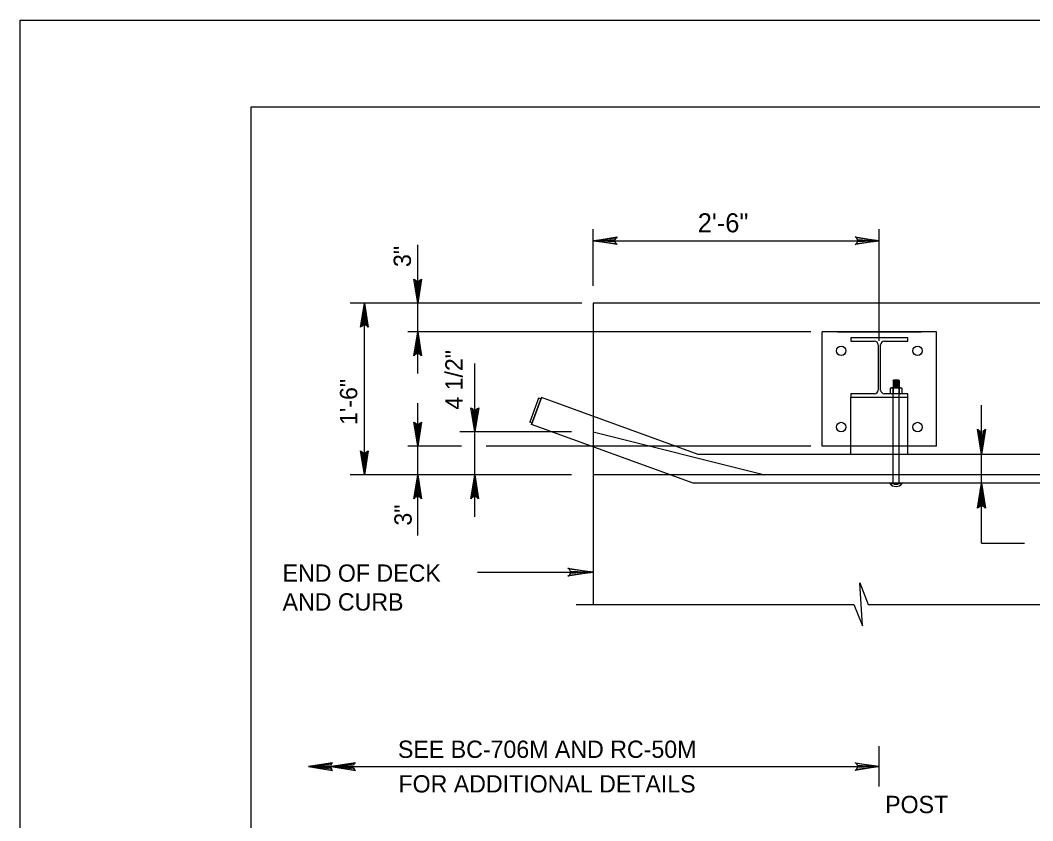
# Model space of a CAD drawing. Extents: x 641054 to 641910, y 298137 to 299325.
# Drawn here: x 641054.5 to 641229.9, y 299186.5 to 299325.4 of the extents above; entities that cross this region are included whole.
import ezdxf

# ---------------------------------------------------------------- set-up
doc = ezdxf.new("R2010")
doc.units = 0
for name, color, linetype in [('1', 7, 'Continuous'), ('2', 7, 'Continuous'), ('Default', 7, 'Continuous'), ('PLT-BNDY', 7, 'Continuous')]:
    doc.layers.add(name, color=color, linetype=linetype)

msp = doc.modelspace()

# ---------------------------------------------------------------- linework, layer by layer
at = {"layer": '1'}
for p, q in [((641205.74, 299262.92), (641205.83, 299263.01)), ((641205.74, 299262.92), (641205.74, 299261.63)), ((641205.74, 299262.92), (641206.77, 299262.92)), ((641205.74, 299262.66), (641206.77, 299262.66)), ((641205.74, 299262.4), (641206.77, 299262.4)), ((641205.82, 299262.79), (641206.69, 299262.79)), ((641205.82, 299262.53), (641206.69, 299262.53)), ((641205.82, 299262.27), (641206.69, 299262.27)), ((641205.83, 299263.01), (641206.69, 299263.01)), ((641206.77, 299262.92), (641206.69, 299263.01)), ((641206.77, 299262.92), (641206.77, 299261.63)), ((641205.4, 299261.63), (641205.26, 299261.55)), ((641205.26, 299261.55), (641205.26, 299260.69)), ((641205.4, 299260.61), (641205.26, 299260.69)), ((641205.4, 299261.63), (641207.12, 299261.63)), ((641207.12, 299260.61), (641205.4, 299260.61)), ((641205.74, 299262.14), (641206.77, 299262.14)), ((641205.74, 299261.89), (641206.77, 299261.89)), ((641205.74, 299261.55), (641205.74, 299260.69)), ((641205.82, 299262.02), (641206.69, 299262.02)), ((641205.82, 299261.76), (641206.69, 299261.76)), ((641206.77, 299261.55), (641206.77, 299260.69)), ((641207.12, 299261.63), (641207.25, 299261.55)), ((641207.12, 299260.61), (641207.25, 299260.69)), ((641207.25, 299261.55), (641207.25, 299260.69)), ((641206.82, 299245.06), (641205.69, 299245.06)), ((641104.45, 299195.95), (641203.36, 299195.95))]:
    msp.add_line(p, q, dxfattribs=at)
for centre, radius, start, end in [((641205.5, 299261.22), 0.409, 54.2974, 89.9999), ((641205.5, 299261.02), 0.409, 269.9985, 305.701), ((641206.26, 299259.85), 1.77, 73.0653, 106.9335), ((641206.26, 299262.39), 1.77, 253.0634, 286.9317), ((641207.01, 299261.22), 0.409, 89.9993, 125.7017), ((641207.01, 299261.02), 0.409, 234.2959, 269.9983)]:
    msp.add_arc(centre, radius, start, end, dxfattribs=at)
at = {"layer": '2'}
for p, q in [((641094.49, 298746.38), (641094.49, 299310.38)), ((641094.49, 299310.38), (641880.49, 299310.38)), ((641144.32, 299259.84), (641142.8, 299255.67)), ((641143.11, 299255.29), (641144.81, 299259.95)), ((641143.11, 299255.29), (641144.81, 299259.95)), ((641144.81, 299259.95), (641143.11, 299255.29)), ((641144.71, 299259.7), (641144.32, 299259.84)), ((641171.95, 299250.07), (641144.81, 299259.95)), ((641171.95, 299250.07), (641144.81, 299259.95)), ((641143.2, 299255.53), (641142.8, 299255.67)), ((641171.08, 299245.11), (641143.11, 299255.29)), ((641171.08, 299245.11), (641143.11, 299255.29)), ((641375.12, 299250.07), (641171.95, 299250.07)), ((641375.12, 299245.11), (641171.08, 299245.11))]:
    msp.add_line(p, q, dxfattribs=at)
for points in [[(641157.74, 299286.64), (641157.59, 299286.93), (641153.76, 299287.14), (641157.74, 299286.64), (641157.94, 299286.47), (641153.76, 299287.14), (641157.59, 299287.33), (641157.73, 299287.61), (641153.76, 299287.14), (641157.94, 299287.8), (641157.73, 299287.61)], [(641199.39, 299287.64), (641199.54, 299287.35), (641203.36, 299287.14), (641199.39, 299287.64), (641199.19, 299287.81), (641203.36, 299287.14), (641199.54, 299286.95), (641199.4, 299286.67), (641203.36, 299287.14), (641199.19, 299286.48), (641199.4, 299286.67)], [(641123.87, 299280.29), (641123.58, 299280.14), (641123.37, 299276.32), (641123.87, 299280.29), (641124.04, 299280.49), (641123.37, 299276.32), (641123.18, 299280.14), (641122.9, 299280.28), (641123.37, 299276.32), (641122.71, 299280.49), (641122.9, 299280.28)], [(641113.62, 299272.34), (641113.9, 299272.49), (641114.12, 299276.32), (641113.62, 299272.34), (641113.44, 299272.14), (641114.12, 299276.32), (641114.3, 299272.5), (641114.59, 299272.36), (641114.12, 299276.32), (641114.78, 299272.14), (641114.59, 299272.36)], [(641122.87, 299267.38), (641123.16, 299267.53), (641123.37, 299271.36), (641122.87, 299267.38), (641122.7, 299267.18), (641123.37, 299271.36), (641123.56, 299267.54), (641123.84, 299267.4), (641123.37, 299271.36), (641124.03, 299267.18), (641123.84, 299267.4)], [(641133.75, 299257.97), (641133.46, 299257.82), (641133.25, 299254), (641133.75, 299257.97), (641133.93, 299258.17), (641133.25, 299254), (641133.06, 299257.82), (641132.78, 299257.96), (641133.25, 299254), (641132.59, 299258.17), (641132.78, 299257.96)], [(641123.87, 299255.49), (641123.58, 299255.34), (641123.37, 299251.52), (641123.87, 299255.49), (641124.04, 299255.69), (641123.37, 299251.52), (641123.18, 299255.34), (641122.9, 299255.48), (641123.37, 299251.52), (641122.71, 299255.69), (641122.9, 299255.48)], [(641221.58, 299254.22), (641221.28, 299254.07), (641221.06, 299250.07), (641221.58, 299254.22), (641221.77, 299254.44), (641221.06, 299250.07), (641220.86, 299254.06), (641220.57, 299254.21), (641221.06, 299250.07), (641220.37, 299254.44), (641220.57, 299254.21)], [(641114.61, 299250.53), (641114.33, 299250.38), (641114.12, 299246.56), (641114.61, 299250.53), (641114.79, 299250.73), (641114.12, 299246.56), (641113.93, 299250.38), (641113.64, 299250.52), (641114.12, 299246.56), (641113.45, 299250.73), (641113.64, 299250.52)], [(641122.87, 299242.58), (641123.16, 299242.73), (641123.37, 299246.55), (641122.87, 299242.58), (641122.7, 299242.38), (641123.37, 299246.55), (641123.56, 299242.73), (641123.84, 299242.59), (641123.37, 299246.55), (641124.03, 299242.38), (641123.84, 299242.59)], [(641132.75, 299242.58), (641133.04, 299242.73), (641133.25, 299246.55), (641132.75, 299242.58), (641132.58, 299242.38), (641133.25, 299246.55), (641133.44, 299242.73), (641133.73, 299242.59), (641133.25, 299246.55), (641133.92, 299242.38), (641133.73, 299242.59)], [(641220.54, 299240.96), (641220.84, 299241.11), (641221.06, 299245.11), (641220.54, 299240.96), (641220.36, 299240.75), (641221.06, 299245.11), (641221.26, 299241.12), (641221.56, 299240.97), (641221.06, 299245.11), (641221.76, 299240.75), (641221.56, 299240.97)], [(641149.61, 299230.16), (641149.77, 299229.86), (641153.76, 299229.64), (641149.61, 299230.16), (641149.4, 299230.34), (641153.76, 299229.64), (641149.77, 299229.44), (641149.62, 299229.14), (641153.76, 299229.64), (641149.4, 299228.94), (641149.62, 299229.14)], [(641108.42, 299196.45), (641108.27, 299196.16), (641104.45, 299195.95), (641108.42, 299196.45), (641108.62, 299196.62), (641104.45, 299195.95), (641108.27, 299195.76), (641108.41, 299195.47), (641104.45, 299195.95), (641108.62, 299195.28), (641108.41, 299195.47)], [(641112.36, 299196.45), (641112.21, 299196.16), (641108.39, 299195.95), (641112.36, 299196.45), (641112.56, 299196.62), (641108.39, 299195.95), (641112.21, 299195.76), (641112.35, 299195.47), (641108.39, 299195.95), (641112.56, 299195.28), (641112.35, 299195.47)], [(641199.39, 299196.45), (641199.54, 299196.16), (641203.36, 299195.95), (641199.39, 299196.45), (641199.19, 299196.62), (641203.36, 299195.95), (641199.54, 299195.76), (641199.4, 299195.47), (641203.36, 299195.95), (641199.19, 299195.28), (641199.4, 299195.47)]]:
    msp.add_lwpolyline(points, dxfattribs=at)
at = {"layer": 'Default'}
for p, q in [((641153.76, 299279.34), (641153.76, 299289.12)), ((641203.36, 299269.76), (641203.36, 299289.12)), ((641153.76, 299287.14), (641203.36, 299287.14)), ((641123.37, 299264.12), (641123.37, 299286.43)), ((641151.78, 299276.32), (641111.67, 299276.32)), ((641151.78, 299276.32), (641112.27, 299276.32)), ((641114.12, 299246.56), (641114.12, 299276.32)), ((641153.76, 299276.32), (641153.76, 299256.69)), ((641375.12, 299276.32), (641153.76, 299276.32)), ((641191.48, 299271.36), (641121.64, 299271.36)), ((641193.44, 299251.52), (641193.44, 299271.36)), ((641213.28, 299271.36), (641193.44, 299271.36)), ((641196.13, 299271.36), (641210.59, 299271.36)), ((641213.28, 299251.52), (641213.28, 299271.36)), ((641208.32, 299270.32), (641198.4, 299270.32)), ((641198.4, 299270.32), (641198.4, 299269.72)), ((641198.4, 299269.72), (641202.51, 299269.72)), ((641204.22, 299269.72), (641208.32, 299269.72)), ((641208.32, 299269.72), (641208.32, 299270.32)), ((641203.15, 299269.08), (641203.15, 299261.25)), ((641203.58, 299261.25), (641203.58, 299269.08)), ((641133.25, 299239.27), (641133.25, 299265.84)), ((641202.51, 299260.61), (641198.4, 299260.61)), ((641198.4, 299260.61), (641198.4, 299259.99)), ((641208.32, 299260.61), (641204.22, 299260.61)), ((641205.74, 299245.11), (641205.74, 299261.63)), ((641206.77, 299245.11), (641206.77, 299261.63)), ((641208.32, 299259.99), (641208.32, 299260.61)), ((641123.37, 299236.01), (641123.37, 299258.96)), ((641198.4, 299259.99), (641208.32, 299259.99)), ((641198.4, 299251.52), (641198.4, 299259.99)), ((641208.32, 299251.52), (641208.32, 299259.99)), ((641221.06, 299234.69), (641221.06, 299258.62)), ((641153.76, 299256.69), (641153.76, 299251.41)), ((641149.99, 299254), (641130.66, 299254)), ((641153.76, 299254), (641183.52, 299246.56)), ((641130.98, 299251.52), (641121.64, 299251.52)), ((641191.48, 299251.52), (641135.23, 299251.52)), ((641153.76, 299251.41), (641153.76, 299224.08)), ((641198.4, 299251.52), (641193.44, 299251.52)), ((641198.4, 299250.07), (641198.4, 299251.52)), ((641208.32, 299251.52), (641198.4, 299251.52)), ((641213.28, 299251.52), (641208.32, 299251.52)), ((641208.32, 299250.07), (641208.32, 299251.52)), ((641149.99, 299246.56), (641111.67, 299246.56)), ((641167.1, 299246.56), (641153.76, 299246.56)), ((641375.12, 299246.56), (641167.1, 299246.56)), ((641205.2, 299245.06), (641205.75, 299245.06)), ((641205.2, 299245.05), (641205.2, 299245.06)), ((641205.2, 299245.05), (641205.75, 299245.05)), ((641205.75, 299245.05), (641205.75, 299245.06)), ((641206.76, 299245.06), (641205.75, 299245.06)), ((641206.76, 299245.06), (641206.76, 299245.05)), ((641206.76, 299245.06), (641207.32, 299245.06)), ((641206.76, 299245.05), (641207.32, 299245.05)), ((641221.06, 299234.69), (641228.54, 299234.69)), ((641133.73, 299229.64), (641153.76, 299229.64)), ((641150.85, 299224.08), (641198.93, 299224.08)), ((641201.41, 299224.08), (641304.27, 299224.08)), ((641203.36, 299192.47), (641203.36, 299199.51))]:
    msp.add_line(p, q, dxfattribs=at)
msp.add_lwpolyline([(641198.93, 299224.08), (641200.44, 299220.36), (641199.99, 299227.8), (641201.41, 299224.08)], dxfattribs=at)
for centre in [(641196.75, 299268.05), (641209.98, 299268.05), (641196.75, 299254.82), (641209.98, 299254.82)]:
    msp.add_circle(centre, 0.827, dxfattribs=at)
for centre, radius, start, end in [((641202.51, 299269.08), 0.636, 0, 90), ((641204.22, 299269.08), 0.636, 90, 180), ((641202.51, 299261.25), 0.636, 270, 0), ((641204.22, 299261.25), 0.636, 180, 270), ((641206.26, 299245.83), 1.32, 216.3703, 323.6297), ((641205.69, 299245.11), 0.0512, 269.9973, 357.2783), ((641206.26, 299245.83), 0.931, 236.9318, 303.0682), ((641206.82, 299245.11), 0.0512, 182.7217, 270.0027)]:
    msp.add_arc(centre, radius, start, end, dxfattribs=at)
for points, degree in [([(641205.78, 299245.06), (641205.77, 299245.06), (641205.75, 299245.07), (641205.74, 299245.1), (641205.74, 299245.11), (641205.74, 299245.11)], 3), ([(641205.74, 299245.11), (641205.74, 299245.11)], 1), ([(641206.77, 299245.11), (641206.77, 299245.11), (641206.77, 299245.1), (641206.77, 299245.07), (641206.75, 299245.06), (641206.74, 299245.06)], 3), ([(641206.77, 299245.11), (641206.77, 299245.11)], 1), ([(641207.32, 299245.06), (641207.32, 299245.05)], 1)]:
    msp.add_open_spline(points, degree=degree, dxfattribs=at)
at = {"layer": 'PLT-BNDY'}
msp.add_lwpolyline([(641054.49, 299325.38), (641895.49, 299325.38), (641895.49, 298731.38), (641054.49, 298731.38)], close=True, dxfattribs=at)

# ---------------------------------------------------------------- texts
at = {"layer": '2'}
for s, height, p in [('2\'-6"', 3.3, (641171.89, 299288.6)), ('END OF DECK', 3, (641099.95, 299228)), ('AND CURB', 3, (641099.95, 299223)), ('SEE BC-706M AND RC-50M', 3.0001, (641119.94, 299197.45)), ('FOR ADDITIONAL DETAILS', 3.0001, (641120.03, 299191.45)), ('  POST', 3, (641202.14, 299187.87))]:
    msp.add_text(s, height=height, dxfattribs=at).set_placement(p)
for s, p in [('3"', (641122.19, 299282.58)), ('4 1/2"', (641131.15, 299257.84)), ('1\'-6"', (641112.89, 299255.19)), ('3"', (641122.32, 299237.73))]:
    msp.add_text(s, height=3, rotation=90, dxfattribs=at).set_placement(p)

doc.saveas('drawing.dxf')
